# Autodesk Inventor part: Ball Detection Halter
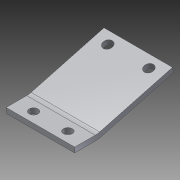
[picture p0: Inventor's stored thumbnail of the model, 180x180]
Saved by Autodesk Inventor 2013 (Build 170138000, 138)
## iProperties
Created: 2012-08
Part Number: Ball Detection Halter
Material: Aluminium 6061
Document SubType Name: Modeling
Designer: rYan
Mass: 2.28685 g
Surface Area: 13.2926 cm^2
Volume: 0.843856 cm^3
Density: 2.71 g/cm^3
Author: rYan
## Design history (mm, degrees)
sketch "Skizze5"
  geometry: L1 (-6, 1.5)-(0, 1.5); L2 (-6, 1.5)-(-6, 0); L3 (-6, 0)-(0, 0); L4 (1.294, 1.67)-(22.544, 7.364); L5 (22.544, 7.364)-(22.933, 5.916); L6 (22.933, 5.916)-(1.682, 0.221); L7 (0, 8.848)-(0, -1.539) reference; A1 r 6.5 centre (0, 6.5) between (0, 0) and (1.682, 0.221); A2 r 5 centre (0, 6.5) between (0, 1.5) and (1.294, 1.67)
  constraints: 12 end point, 4 perpendicular, 4 point on circle, 4 tangent, 2 centre point, 1 horizontal, 1 point on line
  dimensions: "d31" = 1.5 distance of L1.start L2.end; "d33" = 6.5 radius of A1; "d34" = 5 radius of A2 (computed from d33); "d35" = 15 deg angle of L1 L4; "d36" = 22 distance of L5.end L6.end; "d37" = 6 distance of L2.end L3.end
extrude "Extrusion2" new body sketch "Skizze5" stored distance "d38" = 20; taper "d39" = 0 deg
sketch "Skizze6"
  geometry: L1 (0, 0)-(20, 0) reference; L2 (20, 6)-(20, 0) reference; L3 (0, 6)-(20, 6) reference; L4 (0, 0)-(0, 6) reference; L5 (10, 6)-(10, 0); L6 (0, 3)-(20, 3); 2 further points
  constraints: 4 end point, 3 midpoint, 2 point on line, 1 symmetric about line
  dimensions: "d40" = 10 distance of point (15, 3) point (5, 3)
hole "Bohrung4" sketch "Skizze6" at (5, 3), (15, 3) diameter "d42" = 2.6; stored, may be unused: countersink angle "d46" = 90 deg, drill point angle "d48" = 118 deg; dims "d43" = 6, "d44" = 4, "d45" = 2, "d47" = 8
sketch "Skizze7"
  geometry: L1 (0, 0)-(20, 0) reference; L2 (20, 22)-(20, 0) reference; L3 (0, 22)-(20, 22) reference; L4 (0, 0)-(0, 22) reference; L5 (16, 19)-(4, 19); L6 (10, 22)-(10, 0); 1 further point
  constraints: 4 end point, 2 midpoint, 1 perpendicular, 1 symmetric about line
  dimensions: "d49" = 12 distance of L5.start L5.end; "d51" = 3 distance between parallel lines of L3 L5
hole "Bohrung5" sketch "Skizze7" at (4, 19), (16, 19) diameter "d52" = 2.7; stored, may be unused: countersink angle "d56" = 90 deg, drill point angle "d58" = 118 deg; dims "d53" = 6, "d54" = 4, "d55" = 2, "d57" = 8
node "Volumenkörper2"
node "Projizierte Kontur1"
node "Projizierte Kontur2"
